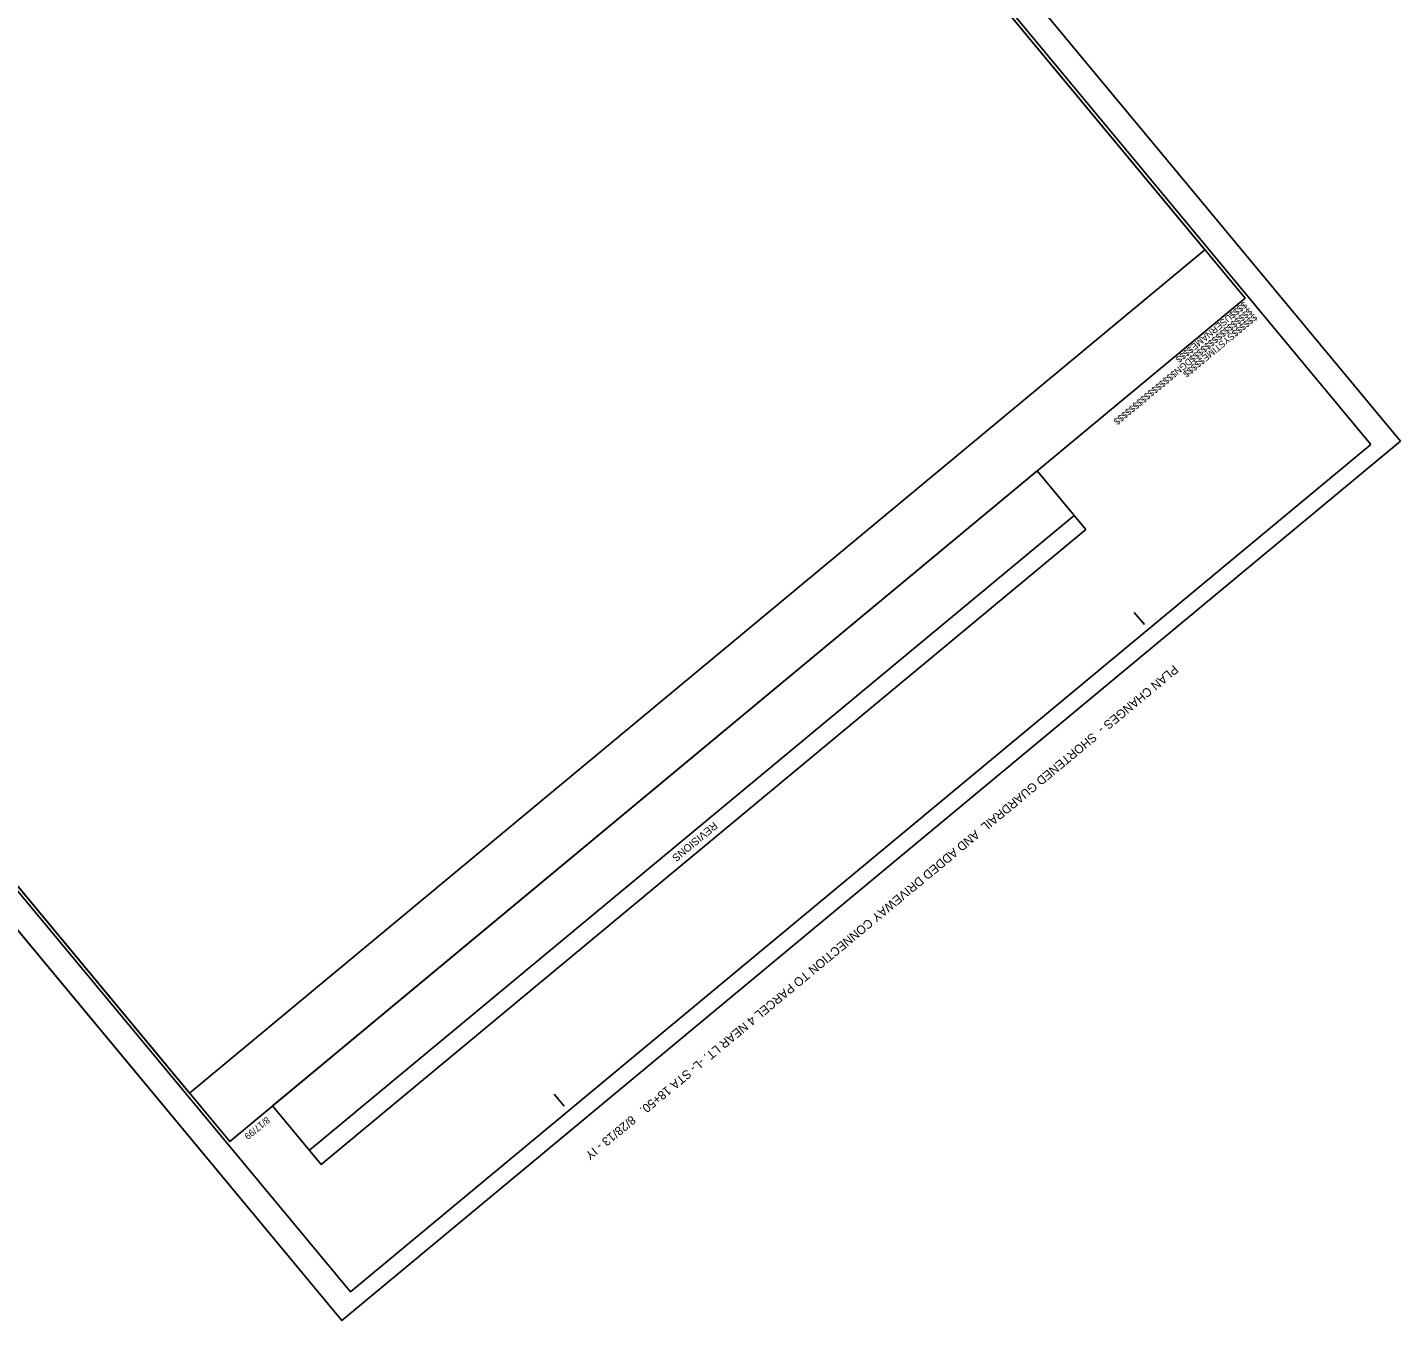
# Model space of a CAD drawing. Extents: x 2597026 to 2598995, y 852197 to 854192.
# Drawn here: x 2597903 to 2598995, y 852197 to 853226 of the extents above; entities that cross this region are included whole.
import ezdxf

# ---------------------------------------------------------------- set-up
doc = ezdxf.new("R2010")
doc.units = 0
for name, color, linetype in [('Prop DSN Text', 7, 'Continuous'), ('Sheet Block Revision CELL', 7, 'Continuous'), ('Sheet Clip Boundary CELL', 7, 'Continuous'), ('Sheet Cutting Line CELL', 7, 'Continuous'), ('Sheet Plan CELL', 7, 'Continuous'), ('Sheet Plan Layout CELL', 7, 'Continuous'), ('Sheet Plot Border Inside CELL', 7, 'Continuous'), ('Sheet Plot Border Outside CELL', 7, 'Continuous')]:
    doc.layers.add(name, color=color, linetype=linetype)

msp = doc.modelspace()

# ---------------------------------------------------------------- linework, layer by layer
at = {"layer": 'Sheet Block Revision CELL'}
msp.add_line((2598735.6, 852837.4), (2598127.3, 852332.3), dxfattribs=at)
msp.add_lwpolyline([(2598744.9, 852826.2), (2598136.6, 852321.1), (2598097.9, 852367.7), (2598706.2, 852872.8)], close=True, dxfattribs=at)
at = {"layer": 'Sheet Clip Boundary CELL'}
msp.add_lwpolyline([(2598839.7, 853048.6), (2597945.3, 854125.7), (2597300.2, 853590), (2597421.1, 853444.4), (2597258.4, 853309.3), (2598031.9, 852377.8)], close=True, dxfattribs=at)
at = {"layer": 'Sheet Cutting Line CELL'}
for p, q in [((2598995.3, 852896.4), (2597919.8, 854191.6)), ((2597077.4, 853492.1), (2598152.9, 852196.9)), ((2598152.9, 852196.9), (2598995.3, 852896.4))]:
    msp.add_line(p, q, dxfattribs=at)
at = {"layer": 'Sheet Plan CELL'}
for p, q in [((2598871.6, 853010.1), (2598871.6, 853010.1)), ((2598791.5, 852750.6), (2598783.5, 852760.2)), ((2598329.9, 852367.3), (2598321.9, 852376.9)), ((2598063.8, 852339.3), (2598063.8, 852339.3))]:
    msp.add_line(p, q, dxfattribs=at)
for points in [[(2597105.5, 853493.4), (2598063.8, 852339.3), (2598871.6, 853010.1), (2597913.3, 854164.1)], [(2598871.6, 853010.1), (2598063.9, 852339.3), (2597233.3, 853339.4), (2597348.8, 853435.3), (2597221, 853589.2), (2597913.3, 854164.1)]]:
    msp.add_lwpolyline(points, close=True, dxfattribs=at)
at = {"layer": 'Sheet Plan Layout CELL'}
msp.add_lwpolyline([(2598063.9, 852339.3), (2598871.6, 853010.1), (2597913.3, 854164.1), (2597268.3, 853628.4), (2597421.1, 853444.4), (2597258.4, 853309.3)], close=True, dxfattribs=at)
at = {"layer": 'Sheet Plot Border Inside CELL'}
msp.add_lwpolyline([(2598971.6, 852893.7), (2597907.3, 854175.3), (2597095.6, 853501.4), (2598160, 852219.7)], close=True, dxfattribs=at)
at = {"layer": 'Sheet Plot Border Outside CELL'}
msp.add_lwpolyline([(2598995.3, 852896.4), (2597919.8, 854191.6), (2597077.4, 853492.1), (2598152.9, 852196.9)], close=True, dxfattribs=at)

# ---------------------------------------------------------------- texts
at = {"layer": 'Prop DSN Text'}
msp.add_text('PLAN CHANGES -  SHORTENED GUARDRAIL  AND ADDED DRIVEWAY CONNECTION TO PARCEL 4 NEAR LT. -L- STA 18+50.   8/28/13 - IY', height=7, rotation=219.7067, dxfattribs=at).set_placement((2598814.8, 852718.8))
at = {"layer": 'Sheet Block Revision CELL'}
msp.add_text('REVISIONS', height=6, rotation=219.7067, dxfattribs=at).set_placement((2598448.8, 852594))
at = {"layer": 'Sheet Plan CELL'}
for s, p in [('$$$$$$$$$$$$$$$$DGN$$$$$$$$$$$$$$$$', (2598874.7, 853002.8)), ('$$$$USERNAME$$$$', (2598870.5, 853007.8)), ('$$$$$$SYSTIME$$$$$', (2598878.6, 852998.1)), ('8/17/99', (2598093, 852359.4))]:
    msp.add_text(s, height=5.25, rotation=219.7067, dxfattribs=at).set_placement(p)

doc.saveas('drawing.dxf')
